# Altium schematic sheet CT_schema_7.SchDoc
size 291 x 250 mm
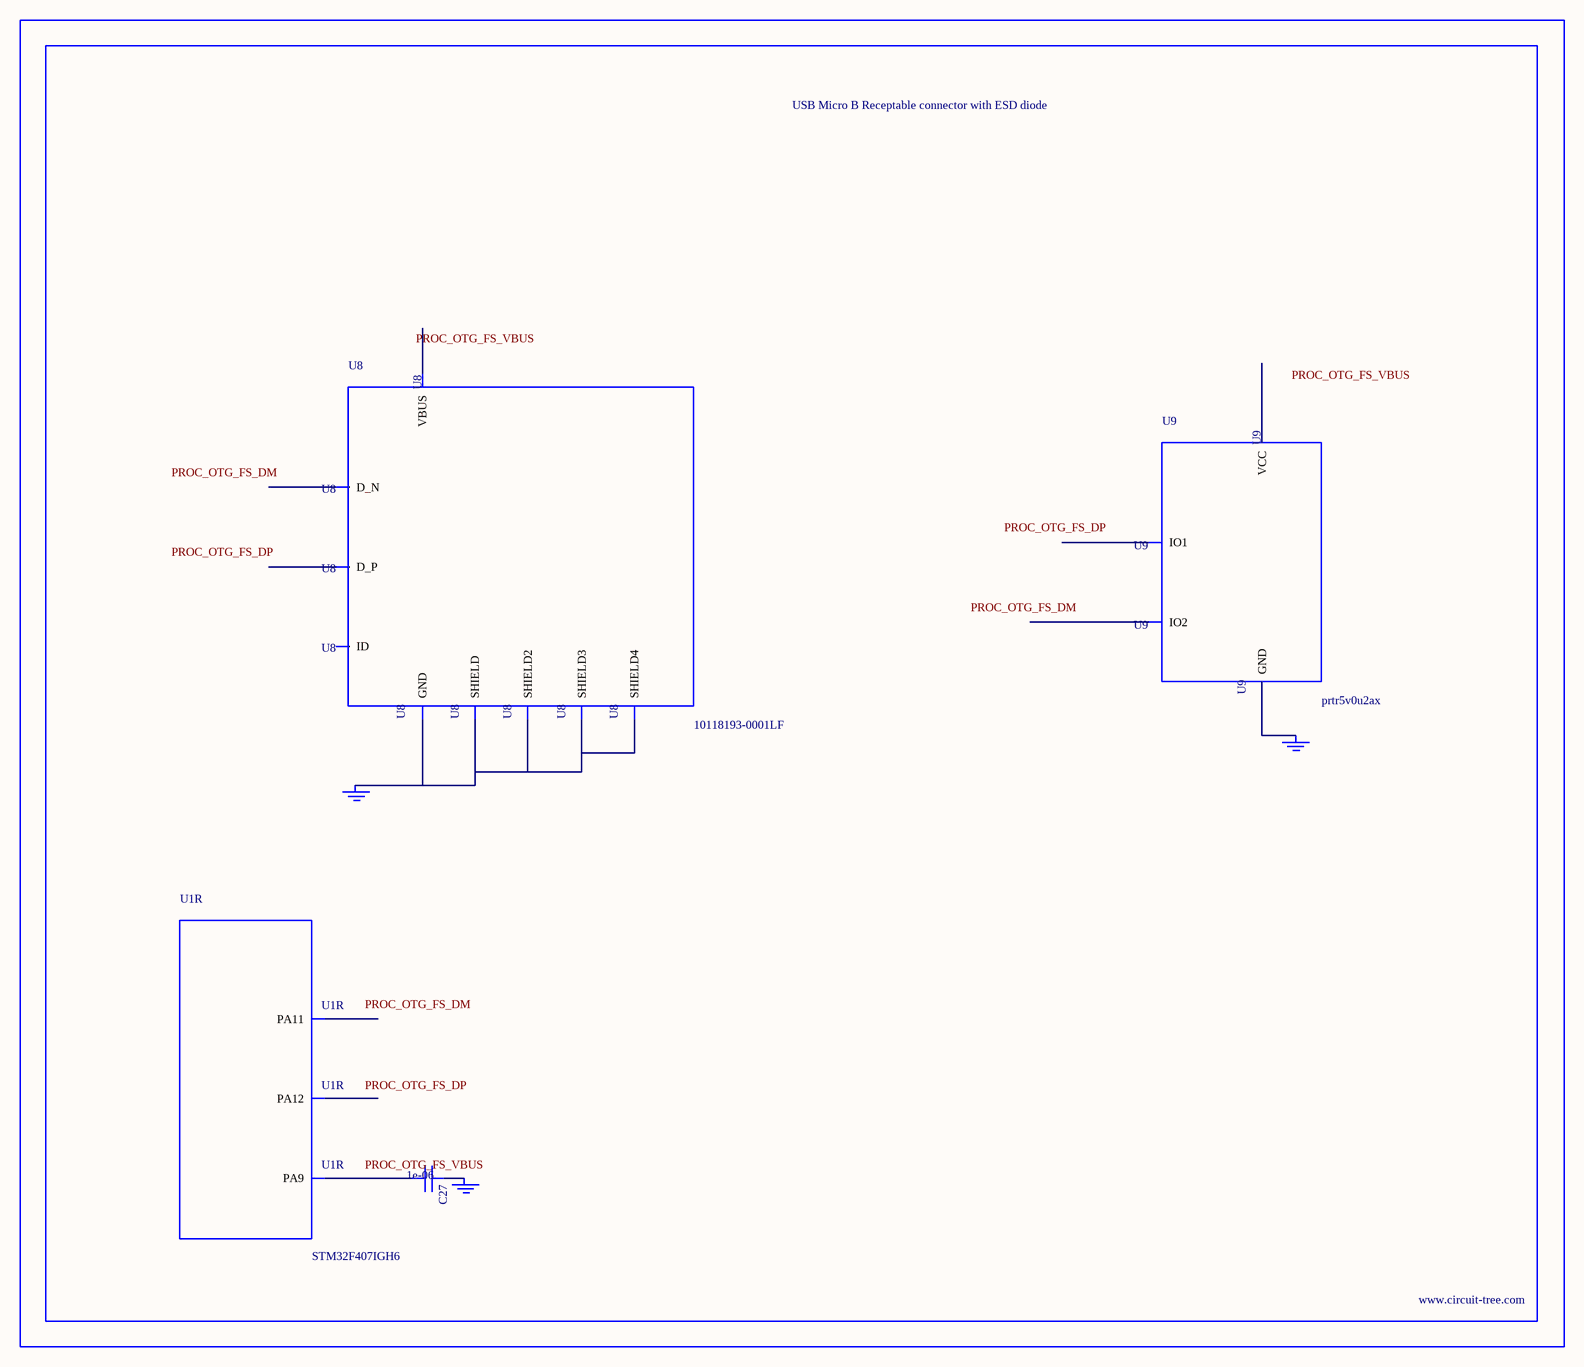
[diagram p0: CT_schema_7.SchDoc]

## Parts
BORDER6  (no value)
C27  1e-06  [C0603]
GND_INSTANCE_6_0  (no value)
GND_INSTANCE_6_1  (no value)
GND_INSTANCE_6_2  (no value)
U1  STM32F407IGH6  [UFBGA176]  (part R of 18)
U8  10118193-0001LF  [FCI_10118193-0001LF]
U9  prtr5v0u2ax  [SOT143B]

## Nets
NetC27_1: C27.1 GND_INSTANCE_6_1.0(GND)
NetC27_2: C27.2 U1.E15(PA9)
NetGND_INSTANCE_6_0_0: GND_INSTANCE_6_0.0(GND) U8.5(GND) U8.6(SHIELD) U8.7(SHIELD2) U8.8(SHIELD3) U8.9(SHIELD4)
NetGND_INSTANCE_6_2_0: GND_INSTANCE_6_2.0(GND) U9.1(GND)

Not connected (* = marked no-connect by the designer): U1 B15(PA12) C15(PA11); U8 1(VBUS) 2(D_N) 3(D_P) 4(ID); U9 2(IO1) 3(IO2) 4(VCC)

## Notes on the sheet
- Labels drawn without touching a wire or pin: PROC_OTG_FS_DM, PROC_OTG_FS_DP, PROC_OTG_FS_VBUS

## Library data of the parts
BORDER6 = BORDER_PAGE6
C27 = C0603C105K3RACTU
GND_INSTANCE_6_0-GND_INSTANCE_6_2 = GND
